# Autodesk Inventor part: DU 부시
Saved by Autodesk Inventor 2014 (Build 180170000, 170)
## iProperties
Created: 2026-09
Part Number: DU 부시
Material: 스테인레스 스틸
Document SubType Name: Modeling
Designer: dg
Density: 8.08 g/cm^3
Appearance: 반연마
Mass: 11.8823 g
Surface Area: 21.4796 cm^2
Volume: 1.47058 cm^3
Author: jhkim
Creation Date: 2026-08-26
Sending System: Autodesk Inventor 2027
Preprocessor: ST-DEVELOPER v20.1
Author: dg
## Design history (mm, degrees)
node "DU 부시1"
node "솔리드1"
node "기준1"
